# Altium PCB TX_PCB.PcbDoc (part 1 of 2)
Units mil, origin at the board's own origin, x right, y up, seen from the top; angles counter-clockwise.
Board outline 2335 x 2060 mil, 2 copper layers (Top Layer, Bottom Layer); 122 components, 95 nets, 483 pads, 219 vias.
Unrouted connection lines stored in the file: 1.
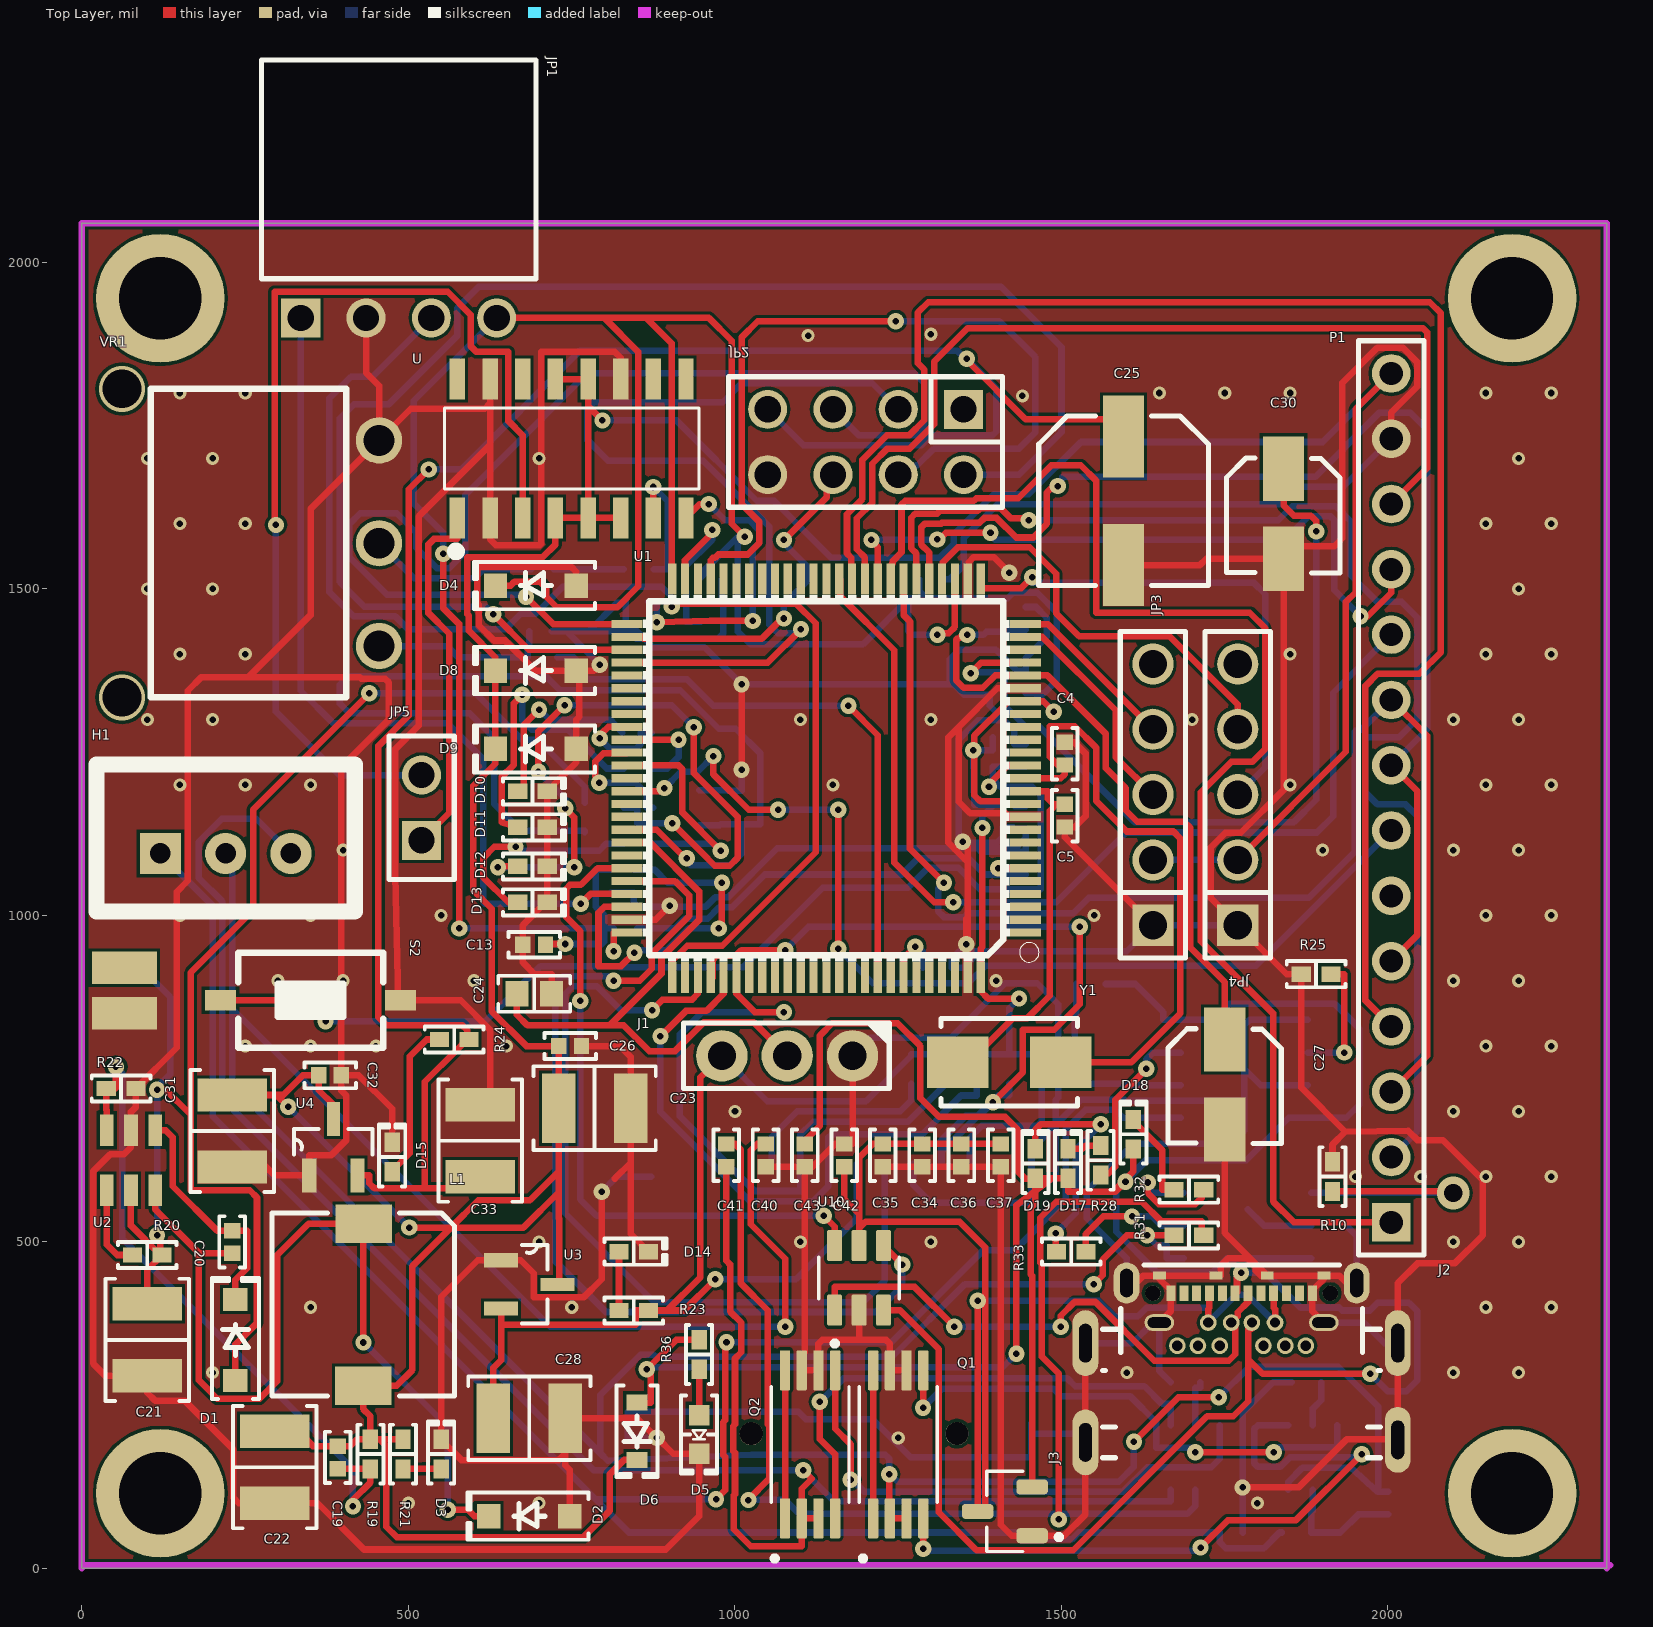
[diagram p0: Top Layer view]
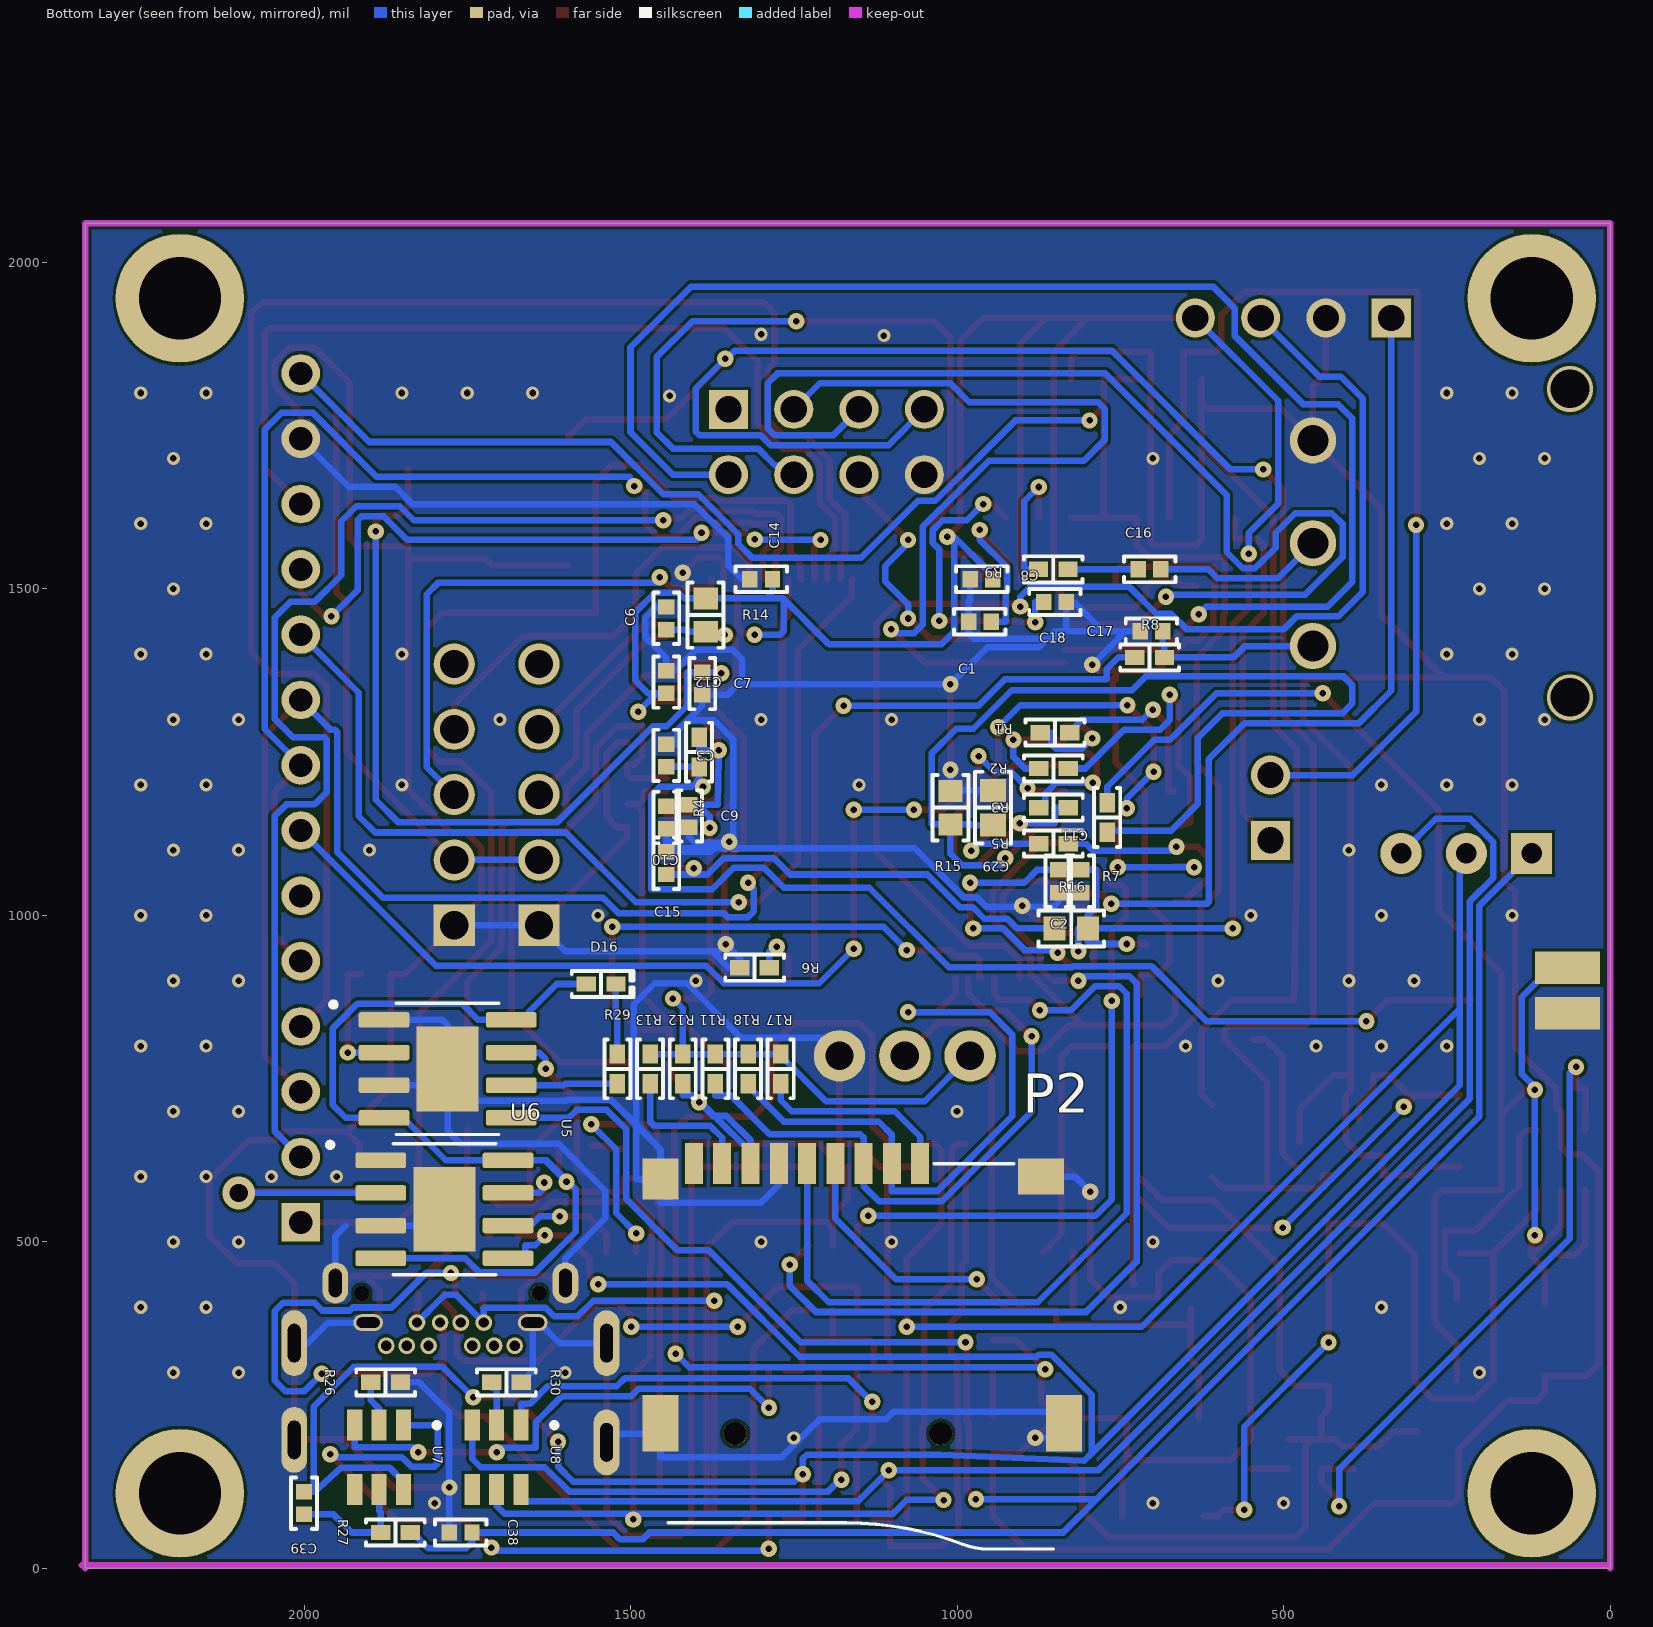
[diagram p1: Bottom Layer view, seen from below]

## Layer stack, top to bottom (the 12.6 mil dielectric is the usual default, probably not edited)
Top Solder: solder mask 0.4, Solder Resist, Dk 3.5
Top Layer: signal copper 1.4
Dielectric 1: dielectric 12.6, FR-4, Dk 4.8
Bottom Layer: signal copper 1.4
Bottom Solder: solder mask 0.4, Solder Resist, Dk 3.5

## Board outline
0,0 0,2060 2335,2060 2335,0

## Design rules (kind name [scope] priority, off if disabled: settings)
Clearance [All] p1: gap=5 ignorepadtopadclearanceinfootprint=FALSE
PolygonConnect PolygonConnect_3 [All vs IsNamedPolygon('GND_L01_P000')] p1: connectstyle=Direct reliefconductorwidth=10 reliefentries=4 polygonreliefangle="90 Angle" airgapwidth=10
PolygonConnect PolygonConnect_2 [All vs IsNamedPolygon('GND_L02_P001')] p2: connectstyle=Direct reliefconductorwidth=10 reliefentries=4 polygonreliefangle="90 Angle" airgapwidth=10
PolygonConnect PolygonConnect_1 [All vs IsNamedPolygon('GND_L01_P000')] p3: connectstyle=Direct reliefconductorwidth=10 reliefentries=4 polygonreliefangle="90 Angle" airgapwidth=10
PolygonConnect [All] p4: connectstyle=Relief reliefconductorwidth=10 reliefentries=4 polygonreliefangle="90 Angle" airgapwidth=10
RoutingVias [All] p1: holewidth=10 width=25 viastyle="Through Hole" minholewidth=10 minwidth=20 maxholewidth=28 maxwidth=50
SolderMaskExpansion [All] p1: expansion=4 istentingtop=FALSE
Width [All] p1: maxlimit=10 minlimit=10 preferedwidth=10
30 further rules are at their usual default settings.

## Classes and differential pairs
component class USB_C: C34 C35 C36 C37 C38 C39 C40 C41 C42 C43 D5 D6 D16 D17 D18 D19 H1 J2 J3 Q1 Q2 R10 R25 R26 R27 R28 R29 R30 R31 R32 R33 R36 U5 U6 U7 U8 U10
component class Audio: C16 C17 C18 JP5 P2 R8 R9 R11 R12 R13 R17 R18 U VR1
component class Power_2: C19 C20 C21 C22 C23 C26 C28 C31 C32 C33 D1 D2 D3 D14 D15 L1 R19 R20 R21 R22 R23 R24 U2 U3 U4
component class MAIN_TX: C1 C2 C3 C4 C5 C6 C7 C8 C9 C10 C11 C12 C13 C14 C15 C24 C25 C27 C29 C30 D4 D8 D9 D10 D11 D12 D13 J1 JP1 JP2 JP3 JP4 P1 R1 R2 R3 R4 R5 R6 R7 R14 R15 R16 S2 U1 Y1

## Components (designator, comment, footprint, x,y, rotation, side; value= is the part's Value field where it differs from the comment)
C1 "2.2 µF" "CAP 0402_1005" 965,1450 r180 bottom
C2 "2.2 µF" "CAP 0402_1005" 845,1052.32 r90 bottom
C3 "0.1 µF" "CAP 0402_1005" 1445,1245 r270 bottom
C4 "20 pF" "CAP 0402_1005" 1505,1247.68 r270 top
C5 "20 pF" "CAP 0402_1005" 1505,1152.68 r90 top
C6 "0.1 µF" "CAP 0402_1005" 1445,1455 r270 bottom
C7 "0.1 µF" "CAP 0402_1005" 1390,1355 r270 bottom
C8 "0.1 µF" "CAP 0402_1005" 962.32,1515 r180 bottom
C9 "0.1 µF" "CAP 0402_1005" 1410,1152.32 r90 bottom
C10 "0.1 µF" "CAP 0402_1005" 1445,1150 r90 bottom
C11 "0.1 µF" "CAP 0402_1005" 810,1052.32 r90 bottom
C12 "0.1 µF" "CAP 0402_1005" 1445,1357.32 r270 bottom
C13 "0.1 µF" "CAP 0402_1005" 692.5,955 r0 top
C14 "0.1 µF" "CAP 0402_1005" 1299.84,1515.12 r180 bottom
C15 "1 µF" "CAP 0402_1005" 1445,1080 r270 bottom
C16 "0.22 µF" "CAP 0402_1005" 705,1530 r0 bottom
C17 "0.1 µF" "CAP 0402_1005" 702.32,1435 r180 bottom
C18 "1 µF" "CAP 0402_1005" 850,1480 r0 bottom
C19 "1000 pF" "CAP 0402_1005" 391.66,170 r90 top
C20 "0.1 µF" "CAP 0402_1005" 230,500 r90 top
C21 "10 µF" "CAP 1210_3225 - 1MM" 100,350 r90 top
C22 "22 µF" "CAP 1210_3225 - 1MM" 295,155 r90 top
C23 "10 µF" "CAP 1210_3225 - 1MM" 785.12,705 r180 top
C24 "0.1 µF" "CAP 0603_1608" 692.5,880 r180 top
C25 "220 µF" "CAP ALSMD 6.6MM H6.1MM" 1595,1635 r270 top
C26 "0.1µF" "CAP 0402_1005" 747.68,800 r180 top
C27 "1 µF" "CAP ALSMD 4.3MM H5.4MM" 1750,741.1 r270 top
C28 "10 µF" "CAP 1210_3225 - 1MM" 685,230 r180 top
C29 "0.1 µF" "CAP 0603_1608" 945,1165 r270 bottom
C30 "1 µF" "CAP ALSMD 4.3MM H5.4MM" 1840,1615 r270 top
C31 "10 µF" "CAP 1210_3225 - 1MM" 230,669.88 r90 top
C32 "0.1µF" "CAP 0402_1005" 380,755 r180 top
C33 "10 µF" "CAP 1210_3225 - 1MM" 610,655 r270 top
C34 "0.1 µF" "CAP 0402_1005" 1286.54,632.68 r270 top
C35 "0.1 µF" "CAP 0402_1005" 1226.26,632.68 r270 top
C36 "0.1 µF" "CAP 0402_1005" 1346.81,632.68 r270 top
C37 "0.1 µF" "CAP 0402_1005" 1407.09,632.68 r270 top
C38 "10 µF" "CAP 0402_1005" 1760,55 r0 bottom
C39 "0.1 µF" "CAP 0402_1005" 2000,100 r90 bottom
C40 "10 µF" "CAP 0402_1005" 1046.81,632.68 r270 top
C41 "0.1 µF" "CAP 0402_1005" 986.54,632.68 r270 top
C42 "1 µF" "CAP 0402_1005" 1167.36,632.68 r270 top
C43 "1 µF" "CAP 0402_1005" 1107.09,632.68 r270 top
D1 "1N5819HW-7-F" SOD-123 235,350 r90 top
D2 "1N5819HW-7-F" SOD-123 685,80 r180 top
D3 "Green" "LED 0402_1005 GREEN" 550,175 r90 top
D4 "1N5819HW-7-F" SOD-123 695,1505 r180 top
D5 "Blue" "LED 0603_1608 BLUE" 945,205 r270 top
D6 "BAT60JFILM" SOD323 850,210 r270 top
D8 "1N5819HW-7-F" SOD-123 695,1375 r180 top
D9 "1N5819HW-7-F" SOD-123 695,1255 r180 top
D10 "Red" "LED 0402_1005 RED" 690,1190 r0 top
D11 "Yellow" "LED 0402_1005 YELLOW" 690,1135 r0 top
D12 "Green" "LED 0402_1005 GREEN" 690,1075 r0 top
D13 "Blue" "LED 0402_1005 BLUE" 690,1020 r0 top
D14 "Yellow" "LED 0402_1005 YELLOW" 845,485 r0 top
D15 "Red" "LED 0402_1005 RED" 475,630 r90 top
D16 "Green" "LED 0402_1005 GREEN" 1545,895 r180 bottom
D17 "Red" "LED 0402_1005 RED" 1510,620 r90 top
D18 "Red" "LED 0402_1005 RED" 1610,665 r90 top
D19 "Green" "LED 0402_1005 GREEN" 1460,620 r90 top
H1 "Header 3P 2.54 Duc Thang" XH2.54M-3 120,1095 r0 top
J1 "M20-7820342" "HARWIN M20-7820345" 1080,785 r270 top
J2 "2129691-1" "TE USB-C 2129691-1" 1775.83,244.21 r180 top
J3 "MCP1700T-5002E/TT" SOT95P237X112-3N#1 1413.27,87.4 r180 top
JP1 "JP 1x4 2.54" "JP 1x4 CC" 485,1915 r0 top
JP2 "JP 2x4 2.54" "JP 2x4 CT" 1200,1725 r180 top
JP3 "JP 1x5 2.54" "JP 1x5 DT" 1640,985 r90 top
JP4 "JP 1x5 2.54" "JP 1x5 DT" 1770,985 r90 top
JP5 "JP 1x2 2.54" "JP 1x2 CT" 520,1115 r90 top
L1 "10µH" "TDK SLF7032" 430.93,403.98 r270 top
P1 "Header 14" HDR1X14 2005,530 r90 top
P2 "ST-TF-003A" SUNTECH_ST-TF-003A 1195,410 r180 bottom
Q1 "FS8205A" SOP65P640X120-8N 1250,190 r90 top
Q2 "FS8205A" SOP65P640X120-8N 1115,190 r90 top
R1 "680 Ohms" "RES 0402_1005" 850,1280 r180 bottom
R2 "680 Ohms" "RES 0402_1005" 852.36,1225 r180 bottom
R3 "680 Ohms" "RES 0402_1005" 852.36,1165 r180 bottom
R4 "100 kOhms" "RES 0402_1005" 1395,1250 r90 bottom
R5 "680 Ohms" "RES 0402_1005" 852.36,1110 r180 bottom
R6 "10 kOhms" "RES 0402_1005" 1310,920 r180 bottom
R7 "10 kOhms" "RES 0402_1005" 770,1150 r90 bottom
R8 "4.7 kOhms" "RES 0402_1005" 705,1395 r0 bottom
R9 "10 kOhms" "RES 0402_1005" 852.64,1530 r0 bottom
R10 "1.2 kOhms" "RES 0402_1005" 1915,600 r270 top
R11 "4.7 kOhms" "RES 0402_1005" 1370,765 r90 bottom
R12 "4.7 kOhms" "RES 0402_1005" 1420,765 r90 bottom
R13 "4.7 kOhms" "RES 0402_1005" 1470,765 r90 bottom
R14 "47 Ohms" "RES 0603_1608" 1385,1460 r270 bottom
R15 "20 kOhms" "RES 0603_1608" 1010,1165 r270 bottom
R16 "0 Ohms" "RES 0603_1608" 825,980 r0 bottom
R17 "4.7 kOhms" "RES 0402_1005" 1270,765 r90 bottom
R18 "4.7 kOhms" "RES 0402_1005" 1320,765 r90 bottom
R19 "52.3 kOhms" "RES 0402_1005" 441.66,175 r90 top
R20 "100 kOhms" "RES 0402_1005" 100,480 r0 top
R21 "1 kOhms" "RES 0402_1005" 491.66,175 r90 top
R22 "10 kOhms" "RES 0402_1005" 60,735 r180 top
R23 "680 Ohms" "RES 0402_1005" 845,395 r0 top
R24 "680 Ohms" "RES 0402_1005" 570,810 r0 top
R25 "1.2 kOhms" "RES 0402_1005" 1890,910 r0 top
R26 "1 kOhms" "RES 0402_1005" 1875,285 r180 bottom
R27 "110 Ohms" "RES 0402_1005" 1860,55 r180 bottom
R28 "1 kOhms" "RES 0402_1005" 1560,625 r90 top
R29 "1 kOhms" "RES 0402_1005" 1520,765 r270 bottom
R30 "1 kOhms" "RES 0402_1005" 1690,285 r180 bottom
R31 "110 Ohms" "RES 0402_1005" 1695,510 r180 top
R32 "1 kOhms" "RES 0402_1005" 1695,580 r180 top
R33 "1 kOhms" "RES 0402_1005" 1515,485 r0 top
R36 "1 kOhms" "RES 0402_1005" 945,327.64 r90 top
S2 "SW-SMD" SW-SMD 350,870 r180 top
U "PAM8403DR" SOIC127P605X150-16N 750,1715 r90 top
U1 "MCU-STM32F407VET6(LQFP100)" LQFP100-0.5-13.8X13.8MM 1140,1210 r180 top
U2 "LM2734YMK" SOT95P285X100-6N 75,625 r270 top
U3 "MCP1700T-3302E/TT" SOT95P237X112-3N#2 685,435 r0 top
U4 "MCP1700T-3302E/TT" SOT95P237X112-3N#2 385,645 r90 top
U5 "TP4056" SOP127P600X175-9N 1780,765 r180 bottom
U6 "TP4056" SOP127P600X175-9N 1785,550 r180 bottom
U7 "DW01A" SOT95P280X145-6N#1 1885,170 r270 bottom
U8 "DW01A" SOT95P280X145-6N#1 1705.04,170 r270 bottom
U10 "USBLC6-2SC6" SOT95P280X145-6N#2 1190,445 r90 top
VR1 "VR 10Kohm" "VR 10kohm" 455,1333.78 r90 top
Y1 "8 MHz" "NDK NX5032GA" 1420,775 r180 top

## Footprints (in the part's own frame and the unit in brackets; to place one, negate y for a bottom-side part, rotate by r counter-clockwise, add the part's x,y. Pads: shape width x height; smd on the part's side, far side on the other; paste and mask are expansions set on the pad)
"CAP 0402_1005" [mm] "Chip Capacitor, 2-Leads, Body 1.02x0.51mm, IPC Medium Density"
  rect 0.6x0.64 smd: 1(-0.44,0) 2(0.44,0)
  silkscreen extent -1,-0.5 1,0.5, body extent -0.5,-0.26 0.5,0.26, height 0.52
"CAP 0603_1608" [mm] "Chip Capacitor, 2-Leads, Body 1.60x0.80mm, IPC Medium Density"
  rect 0.9x1 smd: 1(-0.675,0) 2(0.675,0)
  silkscreen extent -1.4,-0.7 1.4,0.7, body extent -0.8,-0.41 0.8,0.41, height 0.82
"CAP 1210_3225 - 1MM" [mm] "Chip Capacitor, 2-Leads, Body 3.20x2.50mm, IPC Medium Density"
  rect 1.3x2.7 smd: 1(-1.4,0) 2(1.4,0)
  silkscreen extent -2.38,-1.62 2.38,1.62, body extent -1.6,-1.25 1.6,1.25, height 1
"CAP ALSMD 4.3MM H5.4MM" [mm] "Aluminum Electrolytic Capacitor, Body 4.30x4.30x5.40mm, IPC Low Density"
  rect 2.5x1.6 smd: 1(-1.75,0) 2(1.75,0)
  silkscreen extent -2.17,-2.21 2.3,2.2, body extent -2.3,-2.2 2.3,2.2, height 5.4
"CAP ALSMD 6.6MM H6.1MM" [mm] "Aluminum Electrolytic Capacitor, Body 6.60x6.60x6.10mm, IPC Low Density"
  rect 3.2x1.6 smd: 1(-2.5,0) 2(2.5,0)
  silkscreen extent -3.3,-3.3 3.3,3.3, body extent -3.5,-3.3 3.5,3.3, height 6.1
"HARWIN M20-7820345" [mm] "2.54mm DIL PC TAIL PIN HEADER ASSEMBLY"
  round 2 hole 1.1: 1(0,2.54) 2(0,0) 3(0,-2.54)
  silkscreen extent -1.27,-4.03 1.27,4, body extent -1.25,-4.01 1.25,4.01, height 8.5
HDR1X14 [mm] "Connector; Header; 14 Position"
  rect 1.5x1.5 hole 0.9: 1(0,0)
  round 1.5 hole 0.9: 2(2.54,0) 3(5.08,0) 4(7.62,0) 5(10.16,0) 6(12.7,0) 7(15.24,0) 8(17.78,0) 9(20.32,0) 10(22.86,0) 11(25.4,0) 12(27.94,0) 13(30.48,0) 14(33.02,0)
  silkscreen extent -1.27,-1.27 34.29,1.27, body extent -1.27,-1.27 34.29,1.27, height 7
"JP 1x2 CT" [mm] "JP 1x2 CT"
  rect 1.52x1.52 hole 1.02: 1(0,0)
  round 1.52 hole 1.02: 2(2.54,0)
  silkscreen extent -1.52,-1.27 4.06,1.27, body extent -1.52,-1.25 4.06,1.25, height 8.51
"JP 1x4 CC" [mm] "4 pins, 1 row, straight, gold plating"
  rect 1.52x1.52 hole 1.02: 1(-3.81,0)
  round 1.52 hole 1.02: 2(-1.27,0) 3(1.27,0) 4(3.81,0)
  silkscreen extent -5.33,1.52 5.33,10.03, body extent -5.33,-0.25 5.33,10.05, height 2.51
"JP 1x5 DT" [mm] "5 pins, 1 row, straight, gold plating"
  rect 1.6x1.6 hole 1.1: 1(0,0)
  round 1.6 hole 1.1: 2(2.54,0) 3(5.08,0) 4(7.62,0) 5(10.16,0)
  silkscreen extent -1.27,-1.27 11.43,1.27, body extent -1.27,-1.27 11.43,1.27, height 8.54
"JP 2x4 CT" [mm] "8 pins, dual row, straight, gold plating"
  rect 1.52x1.52 hole 1.02: 1(-3.81,-1.27)
  round 1.52 hole 1.02: 2(-1.27,-1.27) 3(1.27,-1.27) 4(3.81,-1.27) 5(3.81,1.27) 6(1.27,1.27) 7(-1.27,1.27) 8(-3.81,1.27)
  silkscreen extent -5.33,-2.54 5.33,2.54, body extent -5.33,-2.54 5.33,2.54, height 8.51
"LED 0402_1005 BLUE" [mm] "Chip Diode, 2-Leads, Body 1.00x0.50mm, IPC Medium Density"
  rect 0.75x0.6 smd: 1(-0.575,0) 2(0.575,0)
  silkscreen extent -1.14,-0.51 1.27,0.51, body extent -0.5,-0.25 0.5,0.25, height 0.21
"LED 0402_1005 GREEN" [mm] "Chip Diode, 2-Leads, Body 1.00x0.50mm, IPC Medium Density"
  rect 0.75x0.6 smd: 1(-0.575,0) 2(0.575,0)
  silkscreen extent -1.14,-0.51 1.27,0.51, body extent -0.5,-0.25 0.5,0.25, height 0.21
"LED 0402_1005 RED" [mm] "Chip Diode, 2-Leads, Body 1.00x0.50mm, IPC Medium Density"
  rect 0.75x0.6 smd: 1(-0.575,0) 2(0.575,0)
  silkscreen extent -1.14,-0.51 1.27,0.51, body extent -0.5,-0.25 0.5,0.25, height 0.21
"LED 0402_1005 YELLOW" [mm] "Chip Diode, 2-Leads, Body 1.00x0.50mm, IPC Medium Density"
  rect 0.75x0.6 smd: 1(-0.575,0) 2(0.575,0)
  silkscreen extent -1.14,-0.51 1.27,0.51, body extent -0.5,-0.25 0.5,0.25, height 0.21
"LED 0603_1608 BLUE" [mm] "Chip Diode, 2-Leads, Body 1.60x0.80mm, IPC Medium Density"
  rect 0.8x0.8 smd: 1(-0.75,0) 2(0.75,0)
  silkscreen extent -1.52,-0.7 1.52,0.7, body extent -0.8,-0.4 0.8,0.4, height 0.53
LQFP100-0.5-13.8X13.8MM [mm]
  rect 1.2x0.32 smd: 1(-7.75,6) 2(-7.75,5.5) 3(-7.75,5) 4(-7.75,4.5) 5(-7.75,4) 6(-7.75,3.5) 7(-7.75,3) 8(-7.75,2.5) 9(-7.75,2) 10(-7.75,1.5) 11(-7.75,1) 12(-7.75,0.5) 13(-7.75,0) 14(-7.75,-0.5) 15(-7.75,-1) 16(-7.75,-1.5) 17(-7.75,-2) 18(-7.75,-2.5) 19(-7.75,-3) 20(-7.75,-3.5) 21(-7.75,-4) 22(-7.75,-4.5) 23(-7.75,-5) 24(-7.75,-5.5) 25(-7.75,-6) 51(7.75,-6) 52(7.75,-5.5) 53(7.75,-5) 54(7.75,-4.5) 55(7.75,-4) 56(7.75,-3.5) 57(7.75,-3) 58(7.75,-2.5) 59(7.75,-2) 60(7.75,-1.5) 61(7.75,-1) 62(7.75,-0.5) 63(7.75,0) 64(7.75,0.5) 65(7.75,1) 66(7.75,1.5) 67(7.75,2) 68(7.75,2.5) 69(7.75,3) 70(7.75,3.5) 71(7.75,4) 72(7.75,4.5) 73(7.75,5) 74(7.75,5.5) 75(7.75,6)
  rect 0.32x1.2 smd: 26(-6,-7.75) 27(-5.5,-7.75) 28(-5,-7.75) 29(-4.5,-7.75) 30(-4,-7.75) 31(-3.5,-7.75) 32(-3,-7.75) 33(-2.5,-7.75) 34(-2,-7.75) 35(-1.5,-7.75) 36(-1,-7.75) 37(-0.5,-7.75) 38(0,-7.75) 39(0.5,-7.75) 40(1,-7.75) 41(1.5,-7.75) 42(2,-7.75) 43(2.5,-7.75) 44(3,-7.75) 45(3.5,-7.75) 46(4,-7.75) 47(4.5,-7.75) 48(5,-7.75) 49(5.5,-7.75) 50(6,-7.75) 76(6,7.75) 77(5.5,7.75) 78(5,7.75) 79(4.5,7.75) 80(4,7.75) 81(3.5,7.75) 82(3,7.75) 83(2.5,7.75) 84(2,7.75) 85(1.5,7.75) 86(1,7.75) 87(0.5,7.75) 88(0,7.75) 89(-0.5,7.75) 90(-1,7.75) 91(-1.5,7.75) 92(-2,7.75) 93(-2.5,7.75) 94(-3,7.75) 95(-3.5,7.75) 96(-4,7.75) 97(-4.5,7.75) 98(-5,7.75) 99(-5.5,7.75) 100(-6,7.75)
  silkscreen extent -8.27,-7.13 7.11,7.15, body extent -8,-8 8,8, height 1.6
"NDK NX5032GA" [mm] "Crystal, 2-Leads, Body 5.00x3.20mm, IPC Medium Density"
  rect 2.4x2 smd: 1(-2,0) 2(2,0)
  silkscreen extent -2.65,-1.7 2.65,1.7, body extent -2.5,-1.6 2.5,1.6, height 1.2
"RES 0402_1005" [mm] "Chip Resistor, 2-Leads, Body 1.0x0.5mm, IPC Medium Density"
  rect 0.75x0.6 smd: 1(-0.575,0) 2(0.575,0)
  silkscreen extent -1.14,-0.51 1.14,0.51, body extent -0.5,-0.25 0.5,0.25, height 0.35
"RES 0603_1608" [mm] "Chip Resistor, 2-Leads, Body 1.60x0.80mm, IPC Medium Density"
  rect 0.85x0.95 smd: 1(-0.65,0) 2(0.65,0)
  silkscreen extent -1.27,-0.7 1.27,0.7, body extent -0.8,-0.4 0.8,0.4, height 0.45
SOD323 [mm] "SOD, 2-Leads, Body 1.25x2.50mm, IPC Medium Density"
  rect 0.625x0.83 smd: 1(-1.113,0) 2(1.113,0)
  silkscreen extent -1.78,-0.8 1.78,0.8, body extent -1.36,-0.62 1.36,0.62, height 1.05
SOD-123 [mm] "SOD, 2-Leads, Body 1.55x3.70mm, IPC Medium Density"
  rect 0.9x0.95 smd: 1(-1.575,0) 2(1.575,0)
  silkscreen extent -2.3,-0.92 2.41,0.92, body extent -1.86,-0.78 1.86,0.77, height 1.35
SOIC127P605X150-16N [mm]
  rect 1.6x0.6 smd: 1(-2.7,4.445) 2(-2.7,3.175) 3(-2.7,1.905) 4(-2.7,0.635) 5(-2.7,-0.635) 6(-2.7,-1.905) 7(-2.7,-3.175) 8(-2.7,-4.445) 9(2.7,-4.445) 10(2.7,-3.175) 11(2.7,-1.905) 12(2.7,-0.635) 13(2.7,0.635) 14(2.7,1.905) 15(2.7,3.175) 16(2.7,4.445)
  silkscreen extent -4.14,-4.95 1.58,4.95
SOP65P640X120-8N [mm]
  rrect25% 1.56x0.4 smd: 1(-2.88,0.975) 2(-2.88,0.325) 3(-2.88,-0.325) 4(-2.88,-0.975) 5(2.88,-0.975) 6(2.88,-0.325) 7(2.88,0.325) 8(2.88,0.975)
  silkscreen extent -4.54,-1.52 2.25,1.52, body extent -3.2,-1.47 3.2,1.46, height 1.2
SOP127P600X175-9N [mm]
  rrect25% 1.97x0.6 smd: 1(-2.475,1.905) 2(-2.475,0.635) 3(-2.475,-0.635) 4(-2.475,-1.905) 5(2.475,-1.905) 6(2.475,-0.635) 7(2.475,0.635) 8(2.475,1.905)
  rect 2.413x3.302 smd paste-3: 9(0,0)
  silkscreen extent -4.54,-2.55 2,2.6, body extent -3,-2.45 3,2.45, height 1.75
SOT95P237X112-3N#1 [mm]
  rrect50% 1.23x0.59 smd: 1(-1.06,0.95) 2(-1.06,-0.95) 3(1.06,0)
  silkscreen extent -2.2,-1.56 0.7,1.56
SOT95P237X112-3N#2 [mm]
  rect 1.321x0.559 smd: 1(-1.092,0.94) 2(-1.092,-0.94)
  rect 1.321x0.508 smd: 3(1.092,0)
  silkscreen extent -0.28,-1.52 0.71,1.53
SOT95P280X145-6N#1 [mm]
  rect 1.21x0.59 smd: 1(-1.255,0.95) 2(-1.255,0) 3(-1.255,-0.95) 4(1.255,-0.95) 5(1.255,0) 6(1.255,0.95)
  silkscreen extent -1.35,2.14 -1.16,2.34, body extent -1.4,-1.45 1.4,1.45, height 1.45
SOT95P280X145-6N#2 [mm]
  rrect25% 1.21x0.59 smd: 1(-1.255,0.95) 2(-1.255,0) 3(-1.255,-0.95) 4(1.255,-0.95) 5(1.255,0) 6(1.255,0.95)
  silkscreen extent -2.65,-1.56 0.81,1.56, body extent -1.53,-1.46 1.27,1.46, height 1.4
SOT95P285X100-6N [mil]
  rect 48x21 smd: 1(-46,37) 2(-46,0) 3(-46,-37) 4(46,-37) 5(46,0) 6(46,37)
SUNTECH_ST-TF-003A [mm]
  rect 0.7x1.6 smd: 1(3.52,5.33) 2(2.42,5.33) 3(1.32,5.33) 4(0.22,5.33) 5(-0.88,5.33) 6(-1.98,5.33) 7(-3.08,5.33) 8(-4.18,5.33) 9(-5.28,5.33)
  rect 1.4x1.6 smd: G1(-6.58,4.73)
  rect 1.4x2.2 smd: G2(-6.58,-4.77) G3(9.12,-4.77)
  rect 1.8x1.4 smd: G4(8.22,4.83)
  round 0.9 hole 0.9 unplated: ""(-3.68,-5.17) ""(4.32,-5.17)
  silkscreen extent -6.29,-9.66 8.7,5.33, body extent -6.78,-9.28 9.32,5.72, height 1.9
SW-SMD [mm] "Switch SMD type"
  rect 1.2x0.8 smd: 1(-3.5,0) 2(3.5,0)
  silkscreen extent -2.82,-1.85 2.82,1.85, body extent -3.05,-1.85 3.05,1.85, height 2.5
"TDK SLF7032" [mm] "Power Inductor, 2-Leads, TDK, SLF7032T-221MR29-2PF"
  rect 1.5x2.2 smd: 1(-3.15,0.013) 2(3.15,-0.013)
  silkscreen extent -3.56,-3.55 3.56,3.55, body extent -3.56,-3.56 3.56,3.54, height 3.39
"TE USB-C 2129691-1" [mm]
  rect 0.35x0.6 smd: A1(2.75,-4.5) A2(2.25,-4.5) A3(1.75,-4.5) A4(1.25,-4.5) A5(0.75,-4.5) A6(0.25,-4.5) A7(-0.25,-4.5) A8(-0.75,-4.5) A9(-1.25,-4.5) A10(-1.75,-4.5) A11(-2.25,-4.5) A12(-2.75,-4.5)
  oval 1.15x0.65 hole 0.4 slot 0.9 at 0 deg: B1(-3.2,-3.36) B12(3.2,-3.36)
  round 0.65 hole 0.4: B2(-2.5,-2.46) B3(-1.7,-2.46) B4(-1.3,-3.36) B5(-0.85,-2.46) B6(-0.4,-3.36) B7(0.4,-3.36) B8(0.85,-2.46) B9(1.3,-3.36) B10(1.7,-2.46) B11(2.5,-2.46)
  round 0.6 hole 0.6 unplated mask+0.102: M(-3.45,-4.5) M(3.45,-4.5)
  oval 1x2.56 hole 0.5 slot 1.5 at 90 deg: S(-6.075,-2.56) S(-6.075,1.2) S(6.075,-2.56) S(6.075,1.3)
  oval 1x1.6 hole 0.5 slot 1.1 at 90 deg: S(-4.475,-4.9) S(4.475,-4.9)
  rect 0.5x0.3 smd: S(-3.2,-5.19) S(-1,-5.19) S(1,-5.19) S(3.2,-5.19)
  silkscreen extent -5.4,-5.6 5.4,1.9, body extent -6.17,-5.3 6.18,5.4, height 3.27
"VR 10kohm" [mm]
  round 1.8 hole 1.2: 0(6,0) 1(2,0) 2(10,0)
  silkscreen extent 0,1.27 12,8.89
XH2.54M-3 [mm]
  rect 1.6x1.6 hole 0.8: 1(0,0)
  round 1.6 hole 0.8: 2(2.54,0) 3(5.08,0)
  silkscreen extent -2.48,-2.26 7.56,3.46, body extent -2.48,-2.26 7.56,3.48, height 6.91

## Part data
C1 C2: library part GRT155C81A225KE13D, "CAP CER 2.2UF 10V X6S 0402", Device Package="0402 (1005 Metric)", Manufacturer="Murata Electronics", Operating Temperature="-55°C ~ 105°C", Ratings=AEC-Q200, Supplier Part Number 1=490-12239-1-ND, Temperature Coefficient=X6S, Tolerance=±10%, Voltage - Rated=10V
C3 C6 C7 C8 C9 C10 C11 C12 C13 C14 C20: library part KGM05AR51A104KN, "CAP CER 0.1UF 10V X5R 0402", Device Package="0402 (1005 Metric)", Manufacturer="KYOCERA AVX", Operating Temperature="-55°C ~ 85°C", Supplier Part Number 1=478-KGM05AR51A104KNCT-ND, Temperature Coefficient=X5R, Tolerance=±10%, Voltage - Rated=10V
C4 C5: library part C0402C200K8GAC7867, "CAP CER 20PF 10V NP0 0402", Device Package="0402 (1005 Metric)", Manufacturer=KEMET, Operating Temperature="-55°C ~ 125°C", Supplier Part Number 1=399-14429-1-ND, Temperature Coefficient="C0G, NP0", Tolerance=±10%, Voltage - Rated=10V
C15: library part GRM155C71A105KE11D, "CAP CER 1UF 10V X7S 0402", Device Package="0402 (1005 Metric)", Manufacturer="Murata Electronics", Operating Temperature="-55°C ~ 125°C", Supplier Part Number 1=490-14457-1-ND, Temperature Coefficient=X7S, Tolerance=±10%, Voltage - Rated=10V
C16: library part 0402X224K100CT, "CAP CER 0.22UF 10V X5R 0402", Device Package="0402 (1005 Metric)", Manufacturer="Walsin Technology Corporation", Operating Temperature="-55°C ~ 85°C", Supplier Part Number 1=1292-1370-1-ND, Temperature Coefficient=X5R, Tolerance=±10%, Voltage - Rated=10V
C17: library part CGA2B2X5R1A104M050BA, "CAP CER 0.1UF 10V X5R 0402", Device Package="0402 (1005 Metric)", Manufacturer="TDK Corporation", Operating Temperature="-55°C ~ 85°C", Ratings=AEC-Q200, Supplier Part Number 1=445-12157-1-ND, Temperature Coefficient=X5R, Tolerance=±20%, Voltage - Rated=10V
C18: library part C0402C105K8PAC7867, "CAP CER 1UF 10V X5R 0402", Device Package="0402 (1005 Metric)", Manufacturer=KEMET, Operating Temperature="-55°C ~ 85°C", Supplier Part Number 1=399-C0402C105K8PAC7867CT-ND, Temperature Coefficient=X5R, Tolerance=±10%, Voltage - Rated=10V
C19: library part LMF105B7102MVHF, "CAP CER 1000PF 10V X7R 0402", Device Package="0402 (1005 Metric)", Manufacturer="Taiyo Yuden", Operating Temperature="-55°C ~ 125°C", Ratings=AEC-Q200, Supplier Part Number 1=587-LMF105B7102MVHFCT-ND, Temperature Coefficient=X7R, Tolerance=±20%, Voltage - Rated=10V
C21 C23 C28 C31 C33: library part CGA6P3X8R1C106M250AB, "CAP CER 10UF 16V X8R 1210", Device Package="1210 (3225 Metric)", Manufacturer="TDK Corporation", Operating Temperature="-55°C ~ 150°C", Ratings=AEC-Q200, Supplier Part Number 1=445-13057-1-ND, Temperature Coefficient=X8R, Tolerance=±20%, Voltage - Rated=16V
C22: library part C1210C226K4RAC7800, "CAP CER 22UF 16V X7R 1210", Device Package="1210 (3225 Metric)", Manufacturer=KEMET, Operating Temperature="-55°C ~ 125°C", Supplier Part Number 1=399-11662-1-ND, Temperature Coefficient=X7R, Tolerance=±10%, Voltage - Rated=16V
C24 C29: library part VJ0603Y104KXQCW1BC, "CAP CER 0.1UF 10V X7R 0603", Device Package="0603 (1608 Metric)", Manufacturer="Vishay Vitramon", Operating Temperature="-55°C ~ 125°C", Supplier Part Number 1=720-1689-1-ND, Temperature Coefficient=X7R, Tolerance=±10%, Voltage - Rated=10V
C25: library part UCM1A221MCL1GS, "CAP ALUM 220UF 20% 10V SMD", Device Package="Radial, Can - SMD", Lifetime @ Temp.="2000 Hrs @ 105°C", Manufacturer=Nichicon, Operating Temperature="-55°C ~ 105°C", Ratings=AEC-Q200, Ripple Current @ High Frequency="300 mA @ 100 kHz", Ripple Current @ Low Frequency="150 mA @ 120 Hz", Supplier Part Number 1=493-17470-1-ND, Tolerance=±20%, Voltage - Rated="10 V"
C26 C32: library part 0402ZC104KAT2A, "CAP CER 0.1UF 10V X7R 0402", Device Package="0402 (1005 Metric)", Manufacturer="AVX Corporation", Operating Temperature="-55°C ~ 125°C", Supplier Part Number 1=478-7891-1-ND, Temperature Coefficient=X7R, Tolerance=±10%, Voltage - Rated=10V
C27 C30: library part EEE-HD1H1R0R, "CAP ALUM 1UF 20% 50V SMD", Device Package="Radial, Can - SMD", Lifetime @ Temp.="5000 Hrs @ 105°C", Manufacturer="Panasonic Electronic Components", Operating Temperature="-40°C ~ 105°C", Ratings=AEC-Q200, Ripple Current @ High Frequency="11.9 mA @ 10 kHz", Ripple Current @ Low Frequency="7 mA @ 120 Hz", Supplier Part Number 1=PCE4972CT-ND, Tolerance=±20%, Voltage - Rated="50 V"
C34 C35 C36 C37 C39: library part KGM05AR71A104KH, "CAP CER 0.1UF 10V X7R 0402", Device Package="0402 (1005 Metric)", Manufacturer="KYOCERA AVX", Operating Temperature="-55°C ~ 125°C", Supplier Part Number 1=478-KGM05AR71A104KHCT-ND, Temperature Coefficient=X7R, Tolerance=±10%, Voltage - Rated=10V
C38 C40: library part CL05A106MP8NUB8, "CAP CER 10UF 10V X5R 0402", Device Package="0402 (1005 Metric)", Manufacturer="Samsung Electro-Mechanics", Operating Temperature="-55°C ~ 85°C", Supplier Part Number 1=1276-6830-1-ND, Temperature Coefficient=X5R, Tolerance=±20%, Voltage - Rated=10V
C41: library part KGM05AV51A104ZH, "CAP CER 0.1UF 10V Y5V 0402", Device Package="0402 (1005 Metric)", Manufacturer="KYOCERA AVX", Operating Temperature="-30°C ~ 85°C", Supplier Part Number 1=478-KGM05AV51A104ZHCT-ND, Temperature Coefficient="Y5V (F)", Tolerance="-20%, +80%", Voltage - Rated=10V
C42 C43: library part KGM05AR51A105KH, "CAP CER 1UF 10V X5R 0402", Device Package="0402 (1005 Metric)", Manufacturer="KYOCERA AVX", Operating Temperature="-55°C ~ 85°C", Supplier Part Number 1=478-CM05X5R105K10AHCT-ND, Temperature Coefficient=X5R, Tolerance=±10%, Voltage - Rated=10V
D1 D2 D4 D8 D9: "DIODE SCHOTTKY 40V 1A SOD123", Capacitance @ Vr, F="60pF @ 4V, 1MHz", Current - Average Rectified (Io)=1A, Current - Reverse Leakage @ Vr="1 mA @ 40 V", Manufacturer="Diodes Incorporated", Operating Temperature - Junction="-65°C ~ 125°C", Package / Case=SOD-123, Supplier Part Number 1=1N5819HW-FDICT-ND, Voltage - DC Reverse (Vr) (Max)="40 V", Voltage - Forward (Vf) (Max) @ If="450 mV @ 1 A"
D3: library part QBLP595-AG15-2897, "LED GREEN CLEAR 0402 SMD", Current - Test=5mA, Device Package="0402 (1005 Metric)", Lens Color=Colorless, Manufacturer="QT Brightek (QTB)", Millicandela Rating=16.5mcd, Supplier Device Package=0402, Supplier Part Number 1=1516-QBLP595-AG15-2897CT-ND, Voltage - Forward (Vf) (Typ)=1.9V
D5: library part 150060BS75000, "LED BLUE CLEAR 0603 SMD", Current - Test=20mA, Device Package="0603 (1608 Metric)", Lens Color=Colorless, Manufacturer="Würth Elektronik", Millicandela Rating=145mcd, Supplier Device Package=0603, Supplier Part Number 1=732-4966-1-ND, Voltage - Forward (Vf) (Typ)=3.2V
D6: "DIODE SCHOTTKY 10V 3A SOD323", Current - Average Rectified (Io)=3A, Current - Reverse Leakage @ Vr="6 µA @ 10 V", Manufacturer=STMicroelectronics, Operating Temperature - Junction="150°C (Max)", Package / Case="SC-76, SOD-323", Supplier Device Package=SOD-323, Supplier Part Number 1=497-3707-1-ND, Voltage - DC Reverse (Vr) (Max)="10 V", Voltage - Forward (Vf) (Max) @ If="580 mV @ 1 A"
D10: library part SM0402RC, "LED RED CLEAR 0402 SMD", Current - Test=20mA, Device Package="0402 (1005 Metric)", Lens Color=Colorless, Manufacturer="Bivar Inc.", Millicandela Rating=90mcd, Supplier Device Package=0402, Supplier Part Number 1=492-2208-1-ND, Voltage - Forward (Vf) (Typ)=2.1V
D11: library part IN-S42ATY, "LED YELLOW CLEAR 0402 SMD", Current - Test=20mA, Device Package="0402 (1005 Metric)", Lens Color=Clear, Manufacturer=Inolux, Millicandela Rating=145mcd, Supplier Device Package=0402, Supplier Part Number 1=1830-1059-1-ND, Voltage - Forward (Vf) (Typ)=1.9V
D12: library part APG1005ZGC-5MAV, "LED GREEN CLEAR 0402 SMD", Current - Test=5mA, Device Package="0402 (1005 Metric)", Lens Color=Colorless, Manufacturer=Kingbright, Millicandela Rating=280mcd, Supplier Device Package=0402, Supplier Part Number 1=754-APG1005ZGC-5MAVCT-ND, Voltage - Forward (Vf) (Typ)=2.85V
D13: library part XZBBR68W5MAV-3, "LED BLUE CLEAR 0402 SMD", Current - Test=5mA, Device Package="0402 (1005 Metric)", Lens Color=Colorless, Manufacturer=SunLED, Millicandela Rating=27mcd, Supplier Device Package=0402, Supplier Part Number 1=1497-1388-1-ND, Voltage - Forward (Vf) (Typ)=2.9V
D14: library part IN-S42BT5Y, "LED YELLOW CLEAR 0402 SMD", Current - Test=5mA, Device Package="0402 (1005 Metric)", Lens Color=0.50mm, Manufacturer=Inolux, Millicandela Rating=23mcd, Supplier Device Package=0402, Supplier Part Number 1=1830-IN-S42BT5YCT-ND, Voltage - Forward (Vf) (Typ)=2V
D15: library part QBLP595-R5, "LED RED CLEAR 0402 SMD", Current - Test=5mA, Device Package="0402 (1005 Metric)", Lens Color=Colorless, Manufacturer="QT Brightek (QTB)", Millicandela Rating=31.5mcd, Supplier Device Package=0402, Supplier Part Number 1=1516-QBLP595-R5CT-ND, Voltage - Forward (Vf) (Typ)=1.85V
D16 D19: library part 150040GS73240, "LED GREEN CLEAR 0402 SMD", Current - Test=20mA, Device Package="0402 (1005 Metric)", Lens Color=Colorless, Manufacturer="Würth Elektronik", Millicandela Rating=800mcd, Supplier Part Number 1=732-11990-1-ND, Voltage - Forward (Vf) (Typ)=3.2V
D17 D18: library part 150040SS73220, "LED RED CLEAR 0402 SMD", Current - Test=20mA, Device Package="0402 (1005 Metric)", Lens Color=Colorless, Manufacturer="Würth Elektronik", Millicandela Rating=90mcd, Supplier Device Package=0402, Supplier Part Number 1=732-13421-1-ND, Voltage - Forward (Vf) (Typ)=2V
H1: "Cắm"
J1: "CONN RCPT 3POS 0.1 GOLD PCB", Current Rating (Amps)=3A, Insulation Color=Black, Manufacturer="Harwin Inc.", Material Flammability Rating="UL94 V-0", Operating Temperature="-40°C ~ 105°C", Supplier Part Number 1=952-1783-ND
J2: "CONN RCPT USB3.1 TYPEC 24POS SMD", Current Rating (Amps)="0.25A, 1.25A, 5A", Manufacturer="TE Connectivity AMP Connectors", Operating Temperature="-30°C ~ 85°C", Supplier Part Number 1=A122008TR-ND, Voltage - Rated=30V
J3: Package=None
JP1: library part "JP 1x4 2.54 Cai Cong", "Cắm"
JP2: library part "JP 2x4 2.54 Cai Thang", "Cắm"
JP3 JP4: library part "JP 1x5 2.54 Duc Thang", "Cắm"
JP5: library part "JP 1x2 2.54 Cai Thang", "Cắm"
L1: library part SLF7032T-100M1R4-2PF, "FIXED IND 10UH 1.4A 63.6 MOHM", Current Rating (Amps)=1.4A, DC Resistance (DCR)="63.6mOhm Max", Device Package=Nonstandard, Inductance Frequency - Test=100kHz, Manufacturer="TDK Corporation", Operating Temperature="-40°C ~ 105°C", Supplier Part Number 1=445-1998-1-ND, Tolerance=±20%
P1: "Header, 14-Pin"
P2: "Micro SD Card Socket", Package=None
Q1 Q2: "N/A", Package=Package
R1 R2 R3 R5 R23 R24: library part RC0402FR-07680RL, "RES 680 OHM 1% 1/16W 0402", Device Package="0402 (1005 Metric)", Manufacturer=Yageo, Operating Temperature="-55°C ~ 155°C", Power (Watts)="0.063W, 1/16W", Supplier Device Package=0402, Supplier Part Number 1=311-680LRCT-ND, Temperature Coefficient=±100ppm/°C, Tolerance=±1%
R4: library part MCS04020D1003BE100, "RES SMD 100K OHM 0.1% 1/16W 0402", Device Package="0402 (1005 Metric)", Manufacturer="Vishay Beyschlag", Operating Temperature="-55°C ~ 125°C", Power (Watts)="0.063W, 1/16W", Supplier Device Package=0402, Supplier Part Number 1=749-1594-1-ND, Temperature Coefficient=±25ppm/°C, Tolerance=±0.1%
R6 R7: library part RP73PF1E10KBTD, "RES 10K OHM 0.1% 1/10W 0402", Device Package="0402 (1005 Metric)", Manufacturer="TE Connectivity Passive Product", Operating Temperature="-55°C ~ 155°C", Power (Watts)="0.1W, 1/10W", Supplier Device Package=0402, Supplier Part Number 1=A127415CT-ND, Temperature Coefficient=±25ppm/°C, Tolerance=±0.1%
R8 R11 R12 R13 R17 R18: library part RK73H1ERTTP4701F, "RES 4.7K OHM 1% 1/10W 0402", Device Package="0402 (1005 Metric)", Manufacturer="KOA Speer Electronics, Inc.", Operating Temperature="-55°C ~ 155°C", Power (Watts)="0.1W, 1/10W", Ratings=AEC-Q200, Supplier Device Package=0402, Supplier Part Number 1=2019-RK73H1ERTTP4701FCT-ND, Temperature Coefficient=±100ppm/°C, Tolerance=±1%
R9 R22: library part MCS0402MC1002FE000, "RES SMD 10K OHM 1% 1/10W 0402", Device Package="0402 (1005 Metric)", Manufacturer="Vishay Beyschlag", Operating Temperature="-55°C ~ 175°C", Power (Watts)="0.1W, 1/10W", Ratings=AEC-Q200, Supplier Device Package=0402, Supplier Part Number 1=MCS0402-10.0K-MFCT-ND, Temperature Coefficient=±50ppm/°C, Tolerance=±1%
R10: library part MCS04020C1201FE000, "RES SMD 1.2K OHM 1% 1/10W 0402", Device Package="0402 (1005 Metric)", Manufacturer="Vishay Beyschlag", Operating Temperature="-55°C ~ 155°C", Power (Watts)="0.1W, 1/10W", Supplier Device Package=0402, Supplier Part Number 1=749-MCS04020C1201FE000CT-ND, Temperature Coefficient=±50ppm/°C, Tolerance=±1%
R14: library part CRT0603-FY-47R0ELF, "RES SMD 47 OHM 1% 1/10W 0603", Device Package="0603 (1608 Metric)", Manufacturer="Bourns Inc.", Operating Temperature="-55°C ~ 155°C", Power (Watts)="0.1W, 1/10W", Supplier Device Package=0603, Supplier Part Number 1=118-CRT0603-FY-47R0ELFCT-ND, Temperature Coefficient=±25ppm/°C, Tolerance=±1%
R15: library part RG1608P-203-B-T5, "RES SMD 20K OHM 0.1% 1/10W 0603", Device Package="0603 (1608 Metric)", Manufacturer=Susumu, Operating Temperature="-55°C ~ 155°C", Power (Watts)="0.1W, 1/10W", Ratings=AEC-Q200, Supplier Device Package=0603, Supplier Part Number 1=RG16P20.0KBCT-ND, Temperature Coefficient=±25ppm/°C, Tolerance=±0.1%
R16: library part CR0603AJ/-000ELF, "RES 0 OHM JUMPER 1/10W 0603", Device Package="0603 (1608 Metric)", Manufacturer="Bourns Inc.", Operating Temperature="-55°C ~ 155°C", Power (Watts)="0.1W, 1/10W", Ratings=AEC-Q200, Supplier Device Package=0603, Supplier Part Number 1=118-CR0603AJ/-000ELFCT-ND, Tolerance=Jumper
R19: library part ERJ-2RKF5232X, "RES SMD 52.3K OHM 1% 1/10W 0402", Device Package="0402 (1005 Metric)", Manufacturer="Panasonic Electronic Components", Operating Temperature="-55°C ~ 155°C", Power (Watts)="0.1W, 1/10W", Ratings=AEC-Q200, Supplier Device Package=0402, Supplier Part Number 1=P52.3KLCT-ND, Temperature Coefficient=±100ppm/°C, Tolerance=±1%
R20: library part RP73PF1E100KBTD, "RES 100K OHM 0.1% 1/10W 0402", Device Package="0402 (1005 Metric)", Manufacturer="TE Connectivity Passive Product", Operating Temperature="-55°C ~ 155°C", Power (Watts)="0.1W, 1/10W", Supplier Device Package=0402, Supplier Part Number 1=A127511CT-ND, Temperature Coefficient=±25ppm/°C, Tolerance=±0.1%
R21: library part MCS0402MC1001FE000, "RES SMD 1K OHM 1% 1/10W 0402", Device Package="0402 (1005 Metric)", Manufacturer="Vishay Beyschlag", Operating Temperature="-55°C ~ 175°C", Power (Watts)="0.1W, 1/10W", Ratings=AEC-Q200, Supplier Device Package=0402, Supplier Part Number 1=MCS0402-1.00K-MFCT-ND, Temperature Coefficient=±50ppm/°C, Tolerance=±1%
R25: library part ERJ-2RKF1201X, "RES SMD 1.2K OHM 1% 1/10W 0402", Device Package="0402 (1005 Metric)", Manufacturer="Panasonic Electronic Components", Operating Temperature="-55°C ~ 155°C", Power (Watts)="0.1W, 1/10W", Ratings=AEC-Q200, Supplier Device Package=0402, Supplier Part Number 1=P1.20KLCT-ND, Temperature Coefficient=±100ppm/°C, Tolerance=±1%
R26: library part RK73H1ERTTP1001F, "RES 1K OHM 1% 1/10W 0402", Device Package="0402 (1005 Metric)", Manufacturer="KOA Speer Electronics, Inc.", Operating Temperature="-55°C ~ 155°C", Power (Watts)="0.1W, 1/10W", Ratings=AEC-Q200, Supplier Device Package=0402, Supplier Part Number 1=2019-RK73H1ERTTP1001FCT-ND, Temperature Coefficient=±100ppm/°C, Tolerance=±1%
R27: library part RK73H1ETTP1100F, "RES 110 OHM 1% 1/10W 0402", Device Package="0402 (1005 Metric)", Manufacturer="KOA Speer Electronics, Inc.", Operating Temperature="-55°C ~ 155°C", Power (Watts)="0.1W, 1/10W", Ratings=AEC-Q200, Supplier Device Package=0402, Supplier Part Number 1=2019-RK73H1ETTP1100FCT-ND, Temperature Coefficient=±100ppm/°C, Tolerance=±1%
R28 R29: library part RK73G1ETTP1001D, "RES 1K OHM 0.5% 1/10W 0402", Device Package="0402 (1005 Metric)", Manufacturer="KOA Speer Electronics, Inc.", Operating Temperature="-55°C ~ 155°C", Power (Watts)="0.1W, 1/10W", Ratings=AEC-Q200, Supplier Device Package=0402, Supplier Part Number 1=2019-RK73G1ETTP1001DCT-ND, Temperature Coefficient=±50ppm/°C, Tolerance=±0.5%
R30: library part CRCW04021K00FKTD, "RES SMD 1K OHM 1% 1/16W 0402", Device Package="0402 (1005 Metric)", Manufacturer="Vishay Dale", Operating Temperature="-55°C ~ 155°C", Power (Watts)="0.063W, 1/16W", Ratings=AEC-Q200, Supplier Device Package=0402, Supplier Part Number 1=541-2957-1-ND, Temperature Coefficient=±100ppm/°C, Tolerance=±1%
R31: library part ERJ-U02F1100X, "RES 110 OHM 1% 1/10W 0402 SMD", Device Package="0402 (1005 Metric)", Manufacturer="Panasonic Electronic Components", Operating Temperature="-55°C ~ 155°C", Power (Watts)="0.1W, 1/10W", Ratings=AEC-Q200, Supplier Device Package=0402, Supplier Part Number 1=10-ERJ-U02F1100XCT-ND, Temperature Coefficient=±200ppm/°C, Tolerance=±1%
R32 R33: library part TNPW04021K00BYEP, "RES 1K OHM 0.1% 1/16W 0402", Device Package="0402 (1005 Metric)", Manufacturer="Vishay Dale", Operating Temperature="-55°C ~ 155°C", Power (Watts)="0.063W, 1/16W", Ratings=AEC-Q200, Supplier Device Package=0402, Supplier Part Number 1=541-4425-1-ND, Temperature Coefficient=±10ppm/°C, Tolerance=±0.1%
R36: library part RMEF0402FT1K00, "RES 1K OHM 1% 1/16W 0402", Device Package="0402 (1005 Metric)", Manufacturer="Stackpole Electronics Inc", Operating Temperature="-55°C ~ 155°C", Power (Watts)="0.063W, 1/16W", Ratings="7C1 RoHS w/out Exemption (100% Pb-Free), AEC-Q200", Supplier Device Package=0402, Supplier Part Number 1=738-RMEF0402FT1K00CT-ND, Temperature Coefficient=±100ppm/°C, Tolerance=±1%
S2: "Switch"
U: "Amplifier IC 2-Channel _Stereo_ Class D 16-SOP", Package="SOP-16 Diodes Inc."
U1: "ARMÂ® CortexÂ®-M4 STM32F4 Microcontroller IC 32-Bit Single-Core 168MHz 512KB (512K x 8) FLASH 100-LQFP (14x14)", Package="LQFP-100 STMicroelectronics"
U2: "Buck Switching Regulator IC Positive Adjustable 0.8V 1 Output 1A SOT-23-6 Thin, TSOT-23-6", Package="SOT-23 Texas Instruments"
U3 U4: "Linear Voltage Regulator IC 1 Output 250mA SOT-23-3", Package="SOT-23-3 Microchip"
U5 U6: "Complete single cell Li-Ion battery with a constant current / constant voltage linear charger", Package=Package
U7 U8: "One Cell Lithium-ion/Polymer Battery Protection IC", Package="SOT-23-6 Fortune Semiconductor"
U10: "17V Clamp 5A (8/20Âµs) Ipp Tvs Diode Surface Mount SOT-23-6", Package="SOT-23-6 STMicroelectronics"
Y1: library part NX5032GA-8.000M-STD-CSU-1, "CRYSTAL 8.0000MHZ 8PF SMD", ESR (Equivalent Series Resistance)="300 Ohms", Frequency Stability=±150ppm, Frequency Tolerance=±50ppm, Load Capacitance=8pF, Manufacturer="NDK America, Inc.", Operating Mode=Fundamental, Operating Temperature="-40°C ~ 150°C", Package / Case="2-SMD, No Lead", Ratings=AEC-Q200, Supplier Part Number 1=644-1132-1-ND

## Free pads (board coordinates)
  round 196.85 hole 125.98: 8(120,115) 8(120,1945) 8(2190,115) 8(2190,1945)
  rect 100x50 all layers, no hole: 9(65,920) 10(65,850)

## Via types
v1: diameter 25, hole 10, Top Layer to Bottom Layer, 130 vias
v2: diameter 20, hole 10, Top Layer to Bottom Layer, 86 vias
v3: diameter 70.87, hole 59.06, Top Layer to Bottom Layer, 2 vias
v4: diameter 50, hole 28, Top Layer to Bottom Layer, 1 vias

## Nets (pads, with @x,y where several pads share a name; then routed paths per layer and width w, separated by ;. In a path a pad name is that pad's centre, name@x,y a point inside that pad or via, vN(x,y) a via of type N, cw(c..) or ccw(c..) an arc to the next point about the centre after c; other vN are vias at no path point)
+5: C19.2 C22.2 C23.2 C26.2 C31.2 C32.2 D6.2 D8.2 D9.2 JP3.2 JP4.2 L1.2 P1.14 R19.2 R21.2 U3.3 U4.3 U.4 U.5 U.6 U.12 U.13 | length 6398.2
  Top Layer w10: C31.2@230,725 298,725 ; C22.2@295,210.12 331,210.12 353.8,187.32 C19.2@391.66,187.32 411,187.32 421.31,197.63 R19.2@441.66,197.63 ; v1(316,707) 298,725 ; U4.3@385,688 385,710 362.68,732.32 C32.2@362.68,755 338.15,755 308.15,725 298,725 ; R21.2@491.66,197.63 456,197.63 ; v1(501,522) 565,522 ; U.13@725,1821.3 U.12@775,1821.3 775,1780 ; U3.3@728,435 730.9,435 730.9,535.13 730,536.02 730,576 ; v1(797,1758) 775,1780 ; U.6@825,1608.7 U.5@775,1608.7 ; D6.2@850,166.2 830.2,166.2 808,144 808,88 768,48 482,48 466,64 466,187.63 456,197.63 ; JP4.2@1770,1085 1935.47,1250.47 1935.47,1480 1950.47,1495 1950.47,1775.47 P1.14@2005,1830 ; R19.2@441.66,197.63 456,197.63 ; R19.2@441.66,197.63 441.66,233 430.44,244.22 L1.2@430.44,279.96 481.96,279.96 506,304 506,463 565,522 ; 565,522 676,522 730,576 ; 565,522 607,564 686,564 730,608 ; 730,576 730,608 ; 730,608 C23.2@730,705 730,752 730.35,752.35 C26.2@730.35,800 680.57,800 627.6,852.97 627.6,1010.19 599.5,1038.29 599.5,1198.71 632.99,1232.21 D9.2@632.99,1255 D8.2@632.99,1375 632.99,1395.51 592.5,1436 592.5,1459.07 590.27,1461.3 590.27,1548.7 705.7,1548.7 725,1568 U.4@725,1608.7 U.5@775,1608.7 ; U.5@775,1608.7 775,1780
  Bottom Layer w10: v1(316,707) v1(501,522) ; v1(797,1758) 910.54,1758 1033.46,1635.08 1059.92,1635.08 1147.58,1547.42 1313.22,1547.42 1335,1569.21 1335,1583.74 1396.26,1645 1450,1645 1530,1725 1900,1725 P1.14@2005,1830 ; JP3.2@1640,1085 JP4.2@1770,1085
+5_USB: C43.1 D6.1 D16.1 D17.1 D18.1 D19.1 J3.2 R36.2 U5.4 U5.8 U6.4 U6.8 | length 3894.1
  Top Layer w10: D6.1@850,253.8 871.34,253.8 871.34,298.66 v1(865,305) 910.28,350.28 R36.2@945,350.28 ; C43.1@1107.09,650 1107.09,655 1130,677.91 1130,816 1149,835 1249,835 1284,800 1284,720 1312.67,691.33 1413.67,691.33 1433,672 1433,608 1444,597 D19.1@1460,597 ; v1(1431,329) 1431,556.36 1460,578.38 ; J3.2@1455,124.8 1455,448.19 1452.6,450.59 1452.6,552.06 1460,559.47 1460,578.38 ; v1(1598,592) 1582.5,576.5 1578.5,576.5 ; D18.1@1610,642.36 1610,608 1578.5,576.5 ; 1460,578.38 D19.1@1460,597 ; 1460,578.38 1469.14,585.32 1485,597.36 ; D19.1@1460,597 D19.1@1460,597.36 1485,597.36 ; 1485,597.36 D17.1@1510,597.36 1510,576.5 1578.5,576.5
  Bottom Layer w10: v1(865,305) 867.99,307.99 1409.99,307.99 v1(1431,329) ; D16.1@1567.64,895 1613,895 1656,852 1656,840 U5.8@1682.56,840 1733,840 1758,865 1918,865 1956.22,826.78 1956.22,710.22 1936,690 U5.4@1877.44,690 1848,690 1783,625 U6.8@1687.56,625 1631,625 ; v1(1598,592) 1631,625 ; U6.4@1882.44,475 1753.18,475 1731.37,453.19 1646.37,453.19 1584,515.55 1584,580.51 1628.49,625 1631,625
